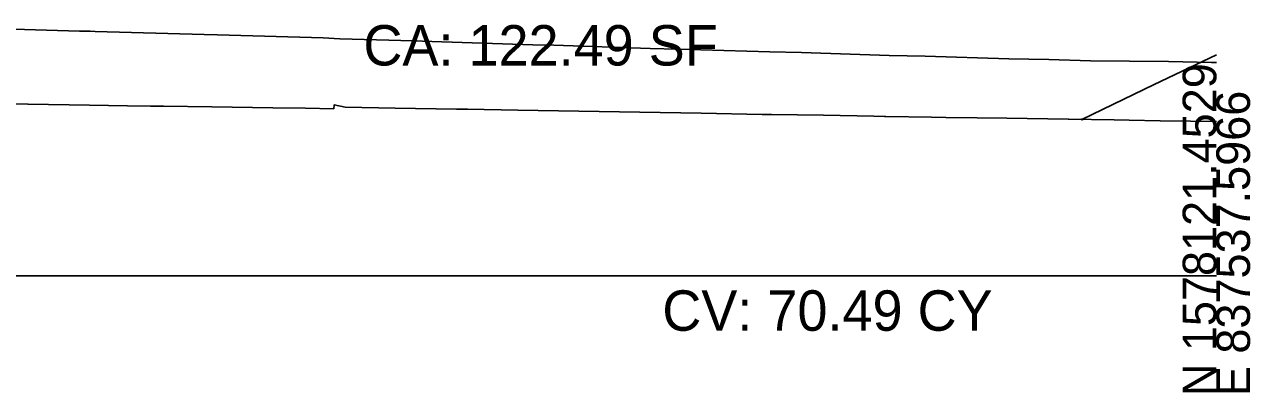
# Model space of a CAD drawing. Extents: x -26 to 303, y -16 to 6048.
# Drawn here: x 200.9 to 302.8, y 3490.3 to 3520.9 of the extents above; entities that cross this region are included whole.
import ezdxf

# ---------------------------------------------------------------- set-up
doc = ezdxf.new("R2010")
doc.units = 0
for name, color, linetype in [('DTM_X_FLOW_ARROWS', 7, 'Continuous'), ('DTM_X_GROUND', 7, 'Continuous'), ('XS_CELL', 7, 'Continuous'), ('XS_P_GROUND', 7, 'Continuous'), ('XS_SHEET_EW_TX_AREA', 7, 'Continuous'), ('XS_SHEET_EW_TX_VOLUME', 7, 'Continuous')]:
    doc.layers.add(name, color=color, linetype=linetype)

msp = doc.modelspace()

# ---------------------------------------------------------------- linework, layer by layer
at = {"layer": 'DTM_X_GROUND'}
msp.add_lwpolyline([(196.28, 3520.63), (205.45, 3520.37), (206.32, 3520.35), (206.76, 3520.34), (215.81, 3520.08), (216.93, 3520.04), (225.72, 3519.79), (227.09, 3519.73), (233.19, 3519.56), (234.75, 3519.5), (243.16, 3519.22), (244.9, 3519.18), (252.92, 3518.92), (255.2, 3518.87), (262.86, 3518.63), (265.5, 3518.57), (272.8, 3518.34), (275.79, 3518.28), (282.75, 3518.06), (286.08, 3517.99), (289.54, 3517.88), (296.01, 3517.84), (299.6, 3517.76), (300, 3517.76)], dxfattribs=at)
msp.add_lwpolyline([(196.28, 3520.63), (205.45, 3520.37), (206.32, 3520.35), (206.76, 3520.34), (215.81, 3520.08), (216.93, 3520.04), (225.72, 3519.79), (227.09, 3519.73), (233.19, 3519.56), (234.75, 3519.5), (243.16, 3519.22), (244.9, 3519.18), (252.92, 3518.92), (255.2, 3518.87), (262.86, 3518.63), (265.5, 3518.57), (272.8, 3518.34), (275.79, 3518.28), (282.75, 3518.06), (286.08, 3517.99), (289.54, 3517.88), (296.01, 3517.84), (299.6, 3517.76), (300, 3517.76)], dxfattribs=at)
at = {"layer": 'XS_CELL'}
msp.add_line((150, 3500), (300, 3500), dxfattribs=at)
at = {"layer": 'XS_P_GROUND'}
for points in [[(288.81, 3513.01), (294.84, 3515.92), (300, 3518.4)], [(198.33, 3514.33), (201.15, 3514.28), (201.18, 3514.28), (206.27, 3514.21), (209.44, 3514.16), (211.36, 3514.13), (212.43, 3514.12), (216.45, 3514.06), (221.54, 3513.98), (224.23, 3513.94), (226.59, 3513.91), (226.62, 3514.23), (227.53, 3514.04), (231.71, 3513.96), (236.8, 3513.88), (237.73, 3513.86), (241.89, 3513.79), (246.97, 3513.7), (252.06, 3513.62), (257.15, 3513.53), (262.23, 3513.44), (262.99, 3513.43), (267.32, 3513.36), (271.52, 3513.29), (272.41, 3513.27), (272.5, 3513.27), (276.3, 3513.21), (277.49, 3513.19), (280.11, 3513.15), (282.58, 3513.11), (287.67, 3513.03), (287.71, 3513.03), (291.49, 3512.97), (292.75, 3512.95), (295.32, 3512.91), (297.84, 3512.87), (300, 3512.84)]]:
    msp.add_lwpolyline(points, dxfattribs=at)

# ---------------------------------------------------------------- texts
at = {"layer": 'DTM_X_FLOW_ARROWS'}
msp.add_text('X', height=0.24, dxfattribs=at).set_placement((288.73, 3512.89))
at = {"layer": 'XS_CELL'}
for s, p in [('N 1578121.4529', (300, 3490)), ('E 837537.5966', (302.8, 3490))]:
    msp.add_text(s, height=2.8, rotation=90, dxfattribs=at).set_placement(p)
at = {"layer": 'XS_SHEET_EW_TX_AREA'}
msp.add_text('CA: 122.49 SF', height=3.36, dxfattribs=at).set_placement((229.06, 3517.5))
at = {"layer": 'XS_SHEET_EW_TX_VOLUME'}
msp.add_text('CV: 70.49 CY', height=3.36, dxfattribs=at).set_placement((253.92, 3495.44))

doc.saveas('drawing.dxf')
